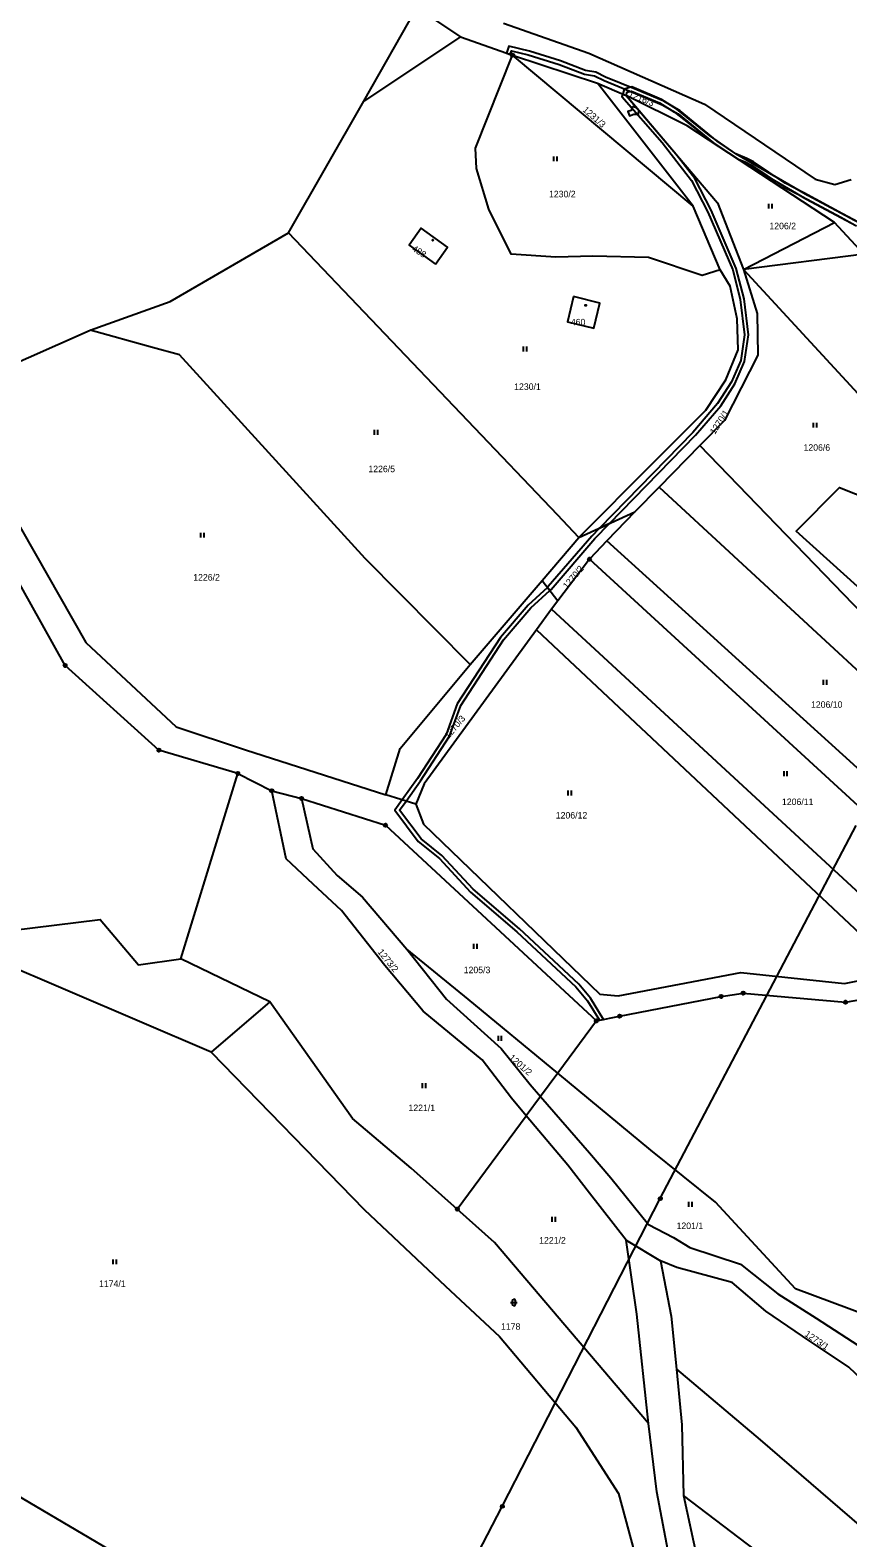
# Model space of a CAD drawing. Extents: x -745926 to -742978, y -968282 to -965689.
# Drawn here: x -745402.1 to -745276.5, y -967417.7 to -967186.3 of the extents above; entities that cross this region are included whole.
import ezdxf

# ---------------------------------------------------------------- set-up
doc = ezdxf.new("R2010")
doc.units = 0
for name, color, linetype in [('Hranice parcel', 7, 'Continuous'), ('Parcelní čísla', 7, 'Continuous'), ('Poz předměty', 7, 'Continuous'), ('Vnitřní kresba', 7, 'Continuous'), ('Věcná břemena k části', 7, 'Continuous'), ('Značky bodu BP', 7, 'Continuous'), ('Značky budov', 7, 'Continuous'), ('Značky kultur', 7, 'Continuous')]:
    doc.layers.add(name, color=color, linetype=linetype)

msp = doc.modelspace()

# ---------------------------------------------------------------- linework, layer by layer
at = {"layer": 'Hranice parcel'}
for p, q in [((-745327.99, -967190.14), (-745314.93, -967194.41)), ((-745300.26, -967213.3), (-745327.99, -967190.14)), ((-745314.93, -967194.41), (-745310.56, -967196.3)), ((-745300.26, -967213.3), (-745314.93, -967194.41)), ((-745296.11, -967223.1), (-745300.26, -967213.3)), ((-745292.54, -967223.04), (-745278.53, -967215.81)), ((-745274.07, -967220.66), (-745278.53, -967215.81)), ((-745415.22, -967242.25), (-745392.88, -967232.34)), ((-745305.48, -967256.46), (-745309.2, -967260.26)), ((-745305.48, -967256.46), (-745245.9, -967311.49)), ((-745317.81, -967264.17), (-745309.2, -967260.26)), ((-745323.47, -967270.79), (-745317.81, -967264.17)), ((-745316.18, -967267.52), (-745321.03, -967273.88)), ((-745316.18, -967267.52), (-745254.4, -967324.19)), ((-745334.49, -967283.69), (-745323.47, -967270.79)), ((-745323.47, -967270.79), (-745321.03, -967273.88)), ((-745324.31, -967278.33), (-745268.41, -967330.85)), ((-745378.97, -967328.84), (-745370.19, -967300.4)), ((-745370.19, -967300.4), (-745364.98, -967303.06)), ((-745364.98, -967303.06), (-745360.41, -967304.23)), ((-745342.87, -967305.11), (-745347.47, -967303.69)), ((-745365.29, -967335.48), (-745378.97, -967328.84)), ((-745315.12, -967338.37), (-745321.05, -967346.4)), ((-745321.05, -967346.4), (-745323.69, -967349.98)), ((-745323.69, -967349.98), (-745325.89, -967352.95)), ((-745336.48, -967367.29), (-745325.89, -967352.95)), ((-745475.73, -967369.05), (-745389.96, -967419.55)), ((-745310.54, -967372.07), (-745305.28, -967375.21))]:
    msp.add_line(p, q, dxfattribs=at)
for points in [[(-745362.41, -967217.42), (-745350.86, -967197.17), (-745342.71, -967182.88)], [(-745342.71, -967182.88), (-745335.97, -967187.34), (-745327.99, -967190.14)], [(-745329.38, -967185.24), (-745316.28, -967189.84), (-745298.54, -967197.66), (-745281.52, -967209.17), (-745278.48, -967209.96), (-745275.99, -967209.2)], [(-745296.11, -967223.1), (-745298.9, -967223.96), (-745307.1, -967221.19), (-745315.66, -967220.97), (-745321.37, -967221.16), (-745328.23, -967220.68), (-745331.64, -967213.78), (-745333.56, -967207.52), (-745333.69, -967204.39), (-745327.99, -967190.14)], [(-745278.53, -967215.81), (-745301.16, -967200.98), (-745310.56, -967196.3)], [(-745310.56, -967196.3), (-745296.54, -967212.81), (-745292.54, -967223.04)], [(-745392.88, -967232.34), (-745380.56, -967227.96), (-745362.41, -967217.42)], [(-745317.81, -967264.17), (-745321.08, -967260.68), (-745362.41, -967217.42)], [(-745339.84, -967222.22), (-745337.98, -967219.62), (-745342.03, -967216.7), (-745343.9, -967219.3), (-745339.84, -967222.22)], [(-745317.81, -967264.17), (-745306.38, -967252.72), (-745298.29, -967244.63), (-745295.23, -967239.98), (-745293.33, -967235.37), (-745293.51, -967230.63), (-745294.59, -967225.6), (-745296.11, -967223.1)], [(-745292.54, -967223.04), (-745290.41, -967229.79), (-745290.34, -967236.2), (-745295.46, -967246.21), (-745299.23, -967250.06), (-745305.48, -967256.46)], [(-745292.54, -967223.04), (-745270.72, -967246.67), (-745265.83, -967256.76)], [(-745318.63, -967227.2), (-745319.56, -967231.07), (-745315.53, -967232.04), (-745314.6, -967228.21), (-745318.63, -967227.2)], [(-745334.49, -967283.69), (-745350.65, -967267.4), (-745379.16, -967236.14), (-745383.3, -967234.99), (-745392.88, -967232.34)], [(-745415.22, -967242.25), (-745393.52, -967280.32), (-745379.67, -967293.23), (-745368.99, -967296.79), (-745347.47, -967303.69)], [(-745370.19, -967300.4), (-745382.3, -967296.82), (-745396.71, -967283.81), (-745418.88, -967244.18)], [(-745247.82, -967296.2), (-745284.44, -967263.18), (-745277.76, -967256.48), (-745270.18, -967259.52), (-745265.83, -967256.76)], [(-745309.2, -967260.26), (-745313.52, -967264.69), (-745316.18, -967267.52)], [(-745321.03, -967273.88), (-745322, -967275.16), (-745324.31, -967278.33)], [(-745468.42, -967276.9), (-745436.1, -967305.72), (-745443.31, -967309.43), (-745415.09, -967325.73), (-745391.34, -967322.84), (-745385.45, -967329.79), (-745378.97, -967328.84)], [(-745324.31, -967278.33), (-745341.55, -967301.99), (-745342.87, -967305.11)], [(-745347.47, -967303.69), (-745345.25, -967296.55), (-745334.49, -967283.69)], [(-745325.89, -967352.95), (-745328.15, -967350.27), (-745332.66, -967344.38), (-745341.73, -967336.91), (-745347.61, -967329.88), (-745354.29, -967321.44), (-745358.6, -967317.4), (-745362.77, -967313.53), (-745364.98, -967303.06)], [(-745360.41, -967304.23), (-745358.66, -967311.95), (-745354.91, -967316.04), (-745351.03, -967319.41), (-745344.25, -967327.38)], [(-745360.41, -967304.23), (-745347.52, -967308.34), (-745315.12, -967338.37)], [(-745342.87, -967305.11), (-745341.66, -967308.19), (-745314.58, -967334.28), (-745311.79, -967334.53), (-745292.96, -967330.93), (-745277.04, -967332.63), (-745271.88, -967331.6), (-745268.41, -967330.85)], [(-745321.05, -967346.4), (-745334.79, -967335.03), (-745344.25, -967327.38)], [(-745344.25, -967327.38), (-745338.16, -967335.05), (-745329.75, -967342.64), (-745325.29, -967348.13), (-745323.69, -967349.98)], [(-745315.12, -967338.37), (-745311.55, -967337.64), (-745295.97, -967334.63), (-745292.57, -967334.12), (-745276.86, -967335.52), (-745262.03, -967332.95), (-745256.05, -967331.01), (-745247.29, -967331.89), (-745245.67, -967332.87), (-745243.44, -967334.45), (-745231.44, -967359.98), (-745229.15, -967366.77), (-745223.7, -967386.99)], [(-745365.29, -967335.48), (-745374.27, -967343.16), (-745350.8, -967367.33), (-745338.32, -967379.11), (-745330, -967386.85), (-745318.3, -967400.73), (-745311.73, -967410.93), (-745306.41, -967430.65)], [(-745336.48, -967367.29), (-745343.58, -967360.98), (-745352.56, -967353.36), (-745365.29, -967335.48)], [(-745242.16, -967435.08), (-745243.92, -967421.19), (-745255.18, -967401.72), (-745270.69, -967384.71), (-745284.55, -967379.5), (-745296.85, -967366.21), (-745306.77, -967358.21), (-745321.05, -967346.4)], [(-745323.69, -967349.98), (-745316.18, -967358.65), (-745312.89, -967362.47), (-745307.1, -967369.65), (-745303.29, -967371.65), (-745300.75, -967373.18), (-745292.97, -967375.75), (-745287.25, -967380.29), (-745281.39, -967384.02), (-745273.92, -967388.83), (-745260.93, -967401.35), (-745248.64, -967423.53), (-745242.16, -967435.08)], [(-745310.54, -967372.07), (-745316.17, -967364.82), (-745319.5, -967360.52), (-745325.89, -967352.95)], [(-745307.11, -967400.17), (-745330.76, -967372.38), (-745336.48, -967367.29)], [(-745307.11, -967400.17), (-745308.93, -967383.39), (-745310.54, -967372.07)], [(-745305.28, -967375.21), (-745303.66, -967383.72), (-745302.82, -967391.87)], [(-745241.32, -967443.39), (-745252.19, -967425.23), (-745264.62, -967402.64), (-745276.34, -967391.56), (-745283.49, -967386.77), (-745289.1, -967382.97), (-745294.27, -967378.56), (-745302.78, -967376.25), (-745305.28, -967375.21)], [(-745302.82, -967391.87), (-745289.96, -967402.7), (-745272.94, -967417.41), (-745260.12, -967438.9), (-745257.81, -967461.8)], [(-745302.82, -967391.87), (-745302, -967400.41), (-745301.73, -967411.25)], [(-745306.41, -967430.65), (-745303.82, -967426.41), (-745303.93, -967420.64), (-745305.86, -967410.66), (-745307.11, -967400.17)], [(-745301.73, -967411.25), (-745299.62, -967420.99), (-745299.26, -967427.83), (-745302.9, -967434.73), (-745308.24, -967437.99), (-745311.03, -967441.5)], [(-745246.89, -967489.1), (-745257.96, -967476.77), (-745263.49, -967469.13), (-745273.11, -967441.52), (-745282.08, -967426.2), (-745301.73, -967411.25)]]:
    msp.add_lwpolyline(points, dxfattribs=at)
at = {"layer": 'Poz předměty'}
for p, q in [((-745305.32, -967365.67), (-745275.21, -967308.39)), ((-745329.57, -967412.91), (-745305.32, -967365.67)), ((-745353.95, -967459.58), (-745329.57, -967412.91))]:
    msp.add_line(p, q, dxfattribs=at)
for centre, radius in [((-745305.32, -967365.67), 0.25), ((-745305.32, -967365.67), 0.2), ((-745305.32, -967365.67), 0.15), ((-745305.32, -967365.67), 0.1), ((-745305.32, -967365.67), 0.05), ((-745329.57, -967412.91), 0.25), ((-745329.57, -967412.91), 0.2), ((-745329.57, -967412.91), 0.15), ((-745329.57, -967412.91), 0.1), ((-745329.57, -967412.91), 0.05)]:
    msp.add_circle(centre, radius, dxfattribs=at)
at = {"layer": 'Vnitřní kresba'}
for p, q in [((-745335.97, -967187.34), (-745350.86, -967197.17)), ((-745274.07, -967220.66), (-745292.54, -967223.04)), ((-745243.28, -967307.95), (-745299.23, -967250.06)), ((-745251.86, -967320.62), (-745313.52, -967264.69)), ((-745263.02, -967329.68), (-745322, -967275.16)), ((-745374.27, -967343.16), (-745415.09, -967325.73))]:
    msp.add_line(p, q, dxfattribs=at)
at = {"layer": 'Věcná břemena k části'}
for points in [[(-745274.94, -967215.77), (-745277.32, -967214.47), (-745283.25, -967211.28), (-745286.12, -967209.79), (-745290.99, -967206.49), (-745292.02, -967205.98), (-745293.73, -967205.27), (-745296.57, -967203.31), (-745302.24, -967198.66), (-745304.75, -967197.19), (-745308.91, -967195.46), (-745313.7, -967193.49), (-745315.22, -967192.74), (-745316.78, -967192.46), (-745320.65, -967191.01), (-745325.42, -967189.5), (-745328.55, -967188.77), (-745328.92, -967189.81), (-745328.36, -967190.01), (-745328.17, -967189.47), (-745325.58, -967190.08), (-745320.85, -967191.57), (-745316.94, -967193.04), (-745315.4, -967193.32), (-745313.94, -967194.03), (-745309.13, -967196.02), (-745305.01, -967197.73), (-745302.58, -967199.16), (-745297.16, -967203.6), (-745293.43, -967206.04), (-745292.26, -967206.52), (-745291.29, -967207.01), (-745286.42, -967210.31), (-745283.53, -967211.82), (-745277.6, -967214.99), (-745275.38, -967216.21)], [(-745274.69, -967215.93), (-745282.67, -967211.69), (-745293.73, -967205.27), (-745297.73, -967202.47), (-745302.77, -967198.4), (-745305.13, -967196.92), (-745309.67, -967195), (-745310.86, -967195.34), (-745311.07, -967196.08), (-745311.19, -967196.49), (-745305.02, -967203.55), (-745300.51, -967209.39), (-745298.01, -967214.21), (-745294.19, -967223.1), (-745293.03, -967227.66), (-745292.36, -967233.07), (-745292.95, -967237.01), (-745294.39, -967240.28), (-745296.5, -967243.58), (-745300.33, -967248.05), (-745314.62, -967262.72), (-745313.11, -967262.04), (-745299.89, -967248.45), (-745296.02, -967243.94), (-745293.85, -967240.56), (-745292.37, -967237.17), (-745291.76, -967233.07), (-745292.43, -967227.54), (-745293.63, -967222.9), (-745297.47, -967213.95), (-745300.01, -967209.07), (-745302.85, -967205.37), (-745310.56, -967196.3), (-745310.38, -967195.82), (-745309.71, -967195.64), (-745305.41, -967197.46), (-745303.11, -967198.88), (-745297.16, -967203.6), (-745293.43, -967206.04), (-745282.97, -967212.21), (-745275.17, -967216.35)]]:
    msp.add_lwpolyline(points, dxfattribs=at)
for points in [[(-745309.56, -967198.02), (-745309.77, -967198.62), (-745310.29, -967198.8), (-745310.05, -967199.46), (-745309.36, -967199.21), (-745308.64, -967199.21), (-745308.62, -967198.59), (-745308.96, -967198.19)], [(-745322.64, -967271.84), (-745322.26, -967272.32), (-745322.09, -967272.16), (-745315.37, -967264.35), (-745313.11, -967262.04), (-745314.62, -967262.72), (-745315.81, -967263.95), (-745322.51, -967271.72)], [(-745322.64, -967271.84), (-745325.62, -967274.56), (-745329.86, -967279.51), (-745336.49, -967289.7), (-745338.2, -967294.4), (-745342.62, -967301.18), (-745344.96, -967304.46), (-745346.09, -967306.04), (-745342.47, -967310.86), (-745339.24, -967313.45), (-745334.45, -967318.61), (-745327.33, -967324.7), (-745318.27, -967333.17), (-745316.51, -967335.28), (-745314.66, -967338.27), (-745314.03, -967338.15), (-745316.03, -967334.92), (-745317.83, -967332.75), (-745326.93, -967324.26), (-745334.03, -967318.17), (-745338.84, -967313.01), (-745342.03, -967310.44), (-745345.35, -967306.04), (-745344.36, -967304.65), (-745342.12, -967301.52), (-745337.66, -967294.66), (-745335.95, -967289.96), (-745329.38, -967279.87), (-745325.18, -967274.98), (-745322.26, -967272.32)]]:
    msp.add_lwpolyline(points, close=True, dxfattribs=at)
at = {"layer": 'Značky bodu BP'}
for centre, radius in [((-745327.99, -967190.14), 0.25), ((-745327.99, -967190.14), 0.0152), ((-745316.18, -967267.52), 0.25), ((-745316.18, -967267.52), 0.0152), ((-745396.71, -967283.81), 0.25), ((-745396.71, -967283.81), 0.0152), ((-745382.3, -967296.82), 0.25), ((-745382.3, -967296.82), 0.0152), ((-745370.19, -967300.4), 0.25), ((-745370.19, -967300.4), 0.0152), ((-745364.98, -967303.06), 0.25), ((-745364.98, -967303.06), 0.0152), ((-745360.41, -967304.23), 0.25), ((-745360.41, -967304.23), 0.0152), ((-745347.52, -967308.34), 0.25), ((-745347.52, -967308.34), 0.0152), ((-745295.97, -967334.63), 0.25), ((-745295.97, -967334.63), 0.0152), ((-745292.57, -967334.12), 0.25), ((-745292.57, -967334.12), 0.0152), ((-745276.86, -967335.52), 0.25), ((-745276.86, -967335.52), 0.0152), ((-745315.12, -967338.37), 0.25), ((-745311.55, -967337.64), 0.25), ((-745311.55, -967337.64), 0.0152), ((-745315.12, -967338.37), 0.0152), ((-745336.48, -967367.29), 0.25), ((-745336.48, -967367.29), 0.0152)]:
    msp.add_circle(centre, radius, dxfattribs=at)
at = {"layer": 'Značky budov'}
for centre in [(-745340.24, -967218.52), (-745316.77, -967228.53)]:
    msp.add_circle(centre, 0.0875, dxfattribs=at)
at = {"layer": 'Značky kultur'}
for p, q in [((-745321.64, -967206.42), (-745321.64, -967205.67)), ((-745321.14, -967206.42), (-745321.14, -967205.67)), ((-745288.63, -967213.69), (-745288.63, -967212.94)), ((-745288.12, -967213.69), (-745288.12, -967212.94)), ((-745326.34, -967235.62), (-745326.34, -967234.87)), ((-745325.83, -967235.62), (-745325.83, -967234.87)), ((-745349.21, -967248.4), (-745349.21, -967247.65)), ((-745348.7, -967248.4), (-745348.7, -967247.65)), ((-745281.76, -967247.31), (-745281.76, -967246.56)), ((-745281.26, -967247.31), (-745281.26, -967246.56)), ((-745375.86, -967264.2), (-745375.86, -967263.45)), ((-745375.35, -967264.2), (-745375.35, -967263.45)), ((-745280.23, -967286.77), (-745280.23, -967286.02)), ((-745279.72, -967286.77), (-745279.72, -967286.02)), ((-745286.3, -967300.81), (-745286.3, -967300.06)), ((-745285.8, -967300.81), (-745285.8, -967300.06)), ((-745319.45, -967303.77), (-745319.45, -967303.02)), ((-745318.95, -967303.77), (-745318.95, -967303.02)), ((-745333.94, -967327.32), (-745333.94, -967326.57)), ((-745333.44, -967327.32), (-745333.44, -967326.57)), ((-745330.17, -967341.44), (-745330.17, -967340.69)), ((-745329.67, -967341.44), (-745329.67, -967340.69)), ((-745341.82, -967348.71), (-745341.82, -967347.96)), ((-745341.32, -967348.71), (-745341.32, -967347.96)), ((-745300.92, -967366.92), (-745300.92, -967366.17)), ((-745300.42, -967366.92), (-745300.42, -967366.17)), ((-745321.92, -967369.23), (-745321.92, -967368.48)), ((-745321.42, -967369.23), (-745321.42, -967368.48)), ((-745389.34, -967375.75), (-745389.34, -967375)), ((-745388.83, -967375.75), (-745388.83, -967375)), ((-745328.29, -967381.61), (-745327.29, -967381.61)), ((-745328.04, -967381.36), (-745328.04, -967381.86)), ((-745327.54, -967381.86), (-745327.54, -967381.36))]:
    msp.add_line(p, q, dxfattribs=at)
for centre, start, end in [((-745327.79, -967381.36), 0, 180), ((-745327.79, -967381.86), 180, 359.9879)]:
    msp.add_arc(centre, 0.25, start, end, dxfattribs=at)

# ---------------------------------------------------------------- texts
at = {"layer": 'Parcelní čísla'}
for s, rotation, p in [('1216/3', 338, (-745310.29, -967196.48)), ('1231/3', 319, (-745317.32, -967198.66)), ('488', 328, (-745343.54, -967220.1)), ('1270/1', 57, (-745296.93, -967248.43)), ('1270/2', 50, (-745319.61, -967272.14)), ('1270/3', 50, (-745337.8, -967295.14)), ('1273/2', 309, (-745348.78, -967327.84)), ('1201/2', 319, (-745328.63, -967344.17)), ('1273/1', 326, (-745283.23, -967386.69))]:
    msp.add_text(s, height=1, rotation=rotation, dxfattribs=at).set_placement(p)
for s, p in [('1230/2', (-745322.4, -967211.95)), ('1206/2', (-745288.55, -967216.85)), ('460', (-745319.05, -967231.61)), ('1230/1', (-745327.75, -967241.52)), ('1206/6', (-745283.31, -967250.86)), ('1226/5', (-745350.14, -967254.15)), ('1226/2', (-745377.04, -967270.79)), ('1206/10', (-745282.16, -967290.32)), ('1206/11', (-745286.62, -967305.25)), ('1206/12', (-745321.36, -967307.32)), ('1205/3', (-745335.5, -967331.06)), ('1221/1', (-745343.98, -967352.23)), ('1201/1', (-745302.81, -967370.34)), ('1221/2', (-745323.91, -967372.57)), ('1174/1', (-745391.51, -967379.23)), ('1178', (-745329.77, -967385.8))]:
    msp.add_text(s, height=1, dxfattribs=at).set_placement(p)

doc.saveas('drawing.dxf')
